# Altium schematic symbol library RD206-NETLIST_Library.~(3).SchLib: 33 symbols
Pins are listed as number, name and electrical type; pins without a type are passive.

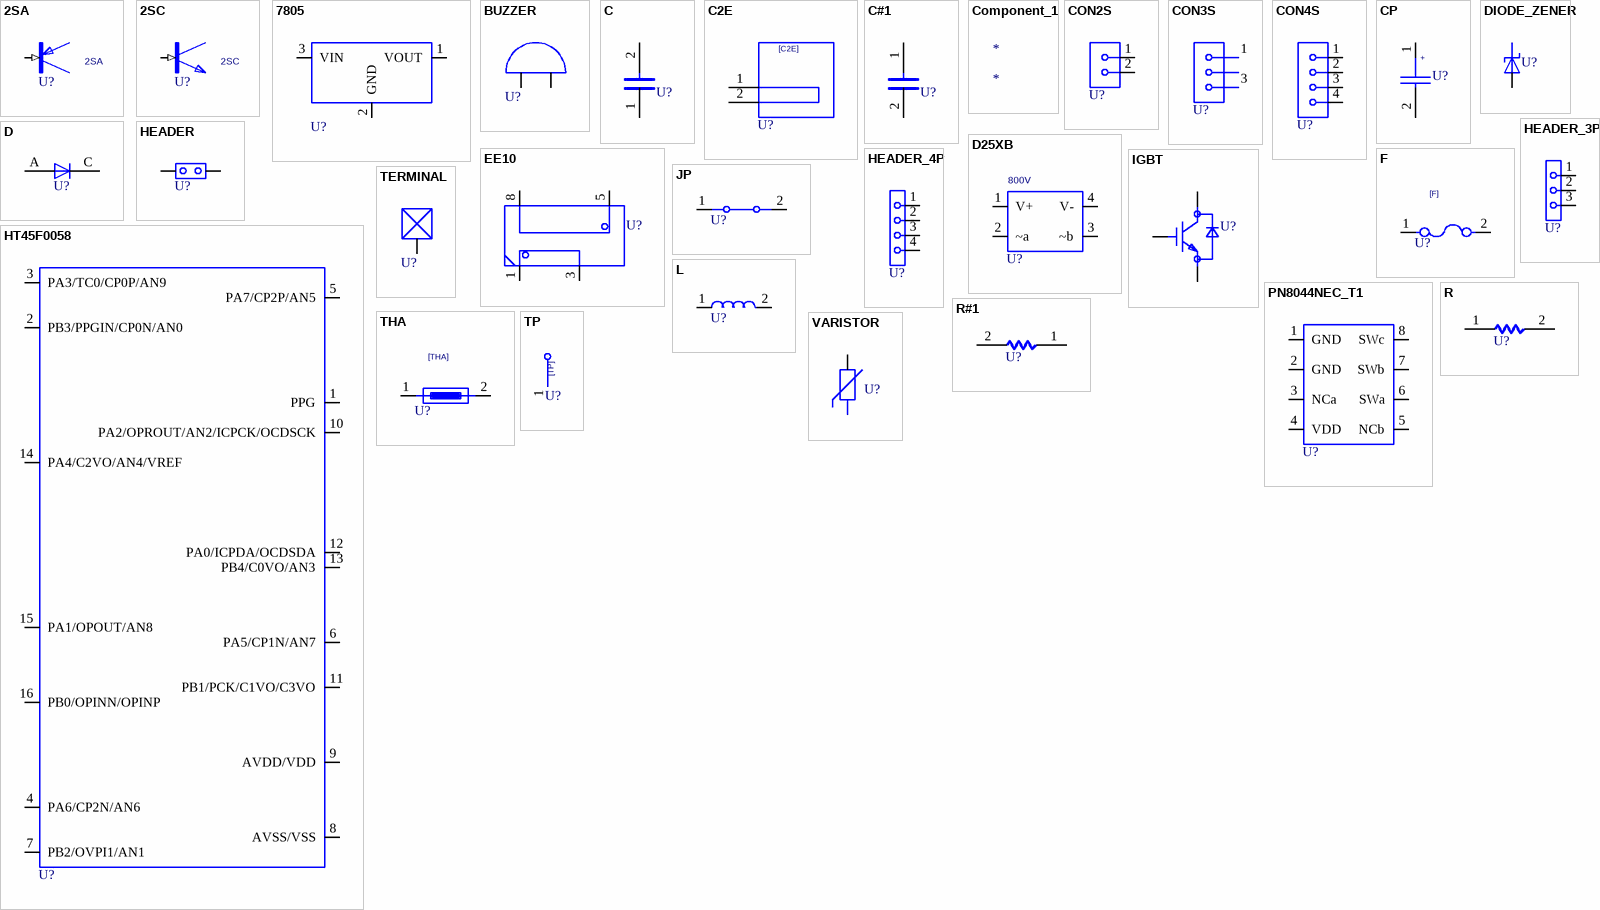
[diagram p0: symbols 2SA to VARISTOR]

## 2SA
designator U?
TIME: 16:07:41; UPDATEUSER: t5459927; SAVECOUNT: 1; OriginalSymbolOrigin: (0,2540); Altium-Right: 20; Altium-Bottom: 40
pins: 1 B (in), 2 E, 3 C

## 2SC
designator U?
TIME: 16:07:41; UPDATEUSER: t5459927; SAVECOUNT: 1; OriginalSymbolOrigin: (0,2540); Altium-Right: 20; Altium-Bottom: 40
pins: 1 B (in), 2 E, 3 C

## 7805
designator U?  (value not drawn)
TIME: 16:07:41; UPDATEUSER: t5459927; UPDATETIME: 09:17:01; SAVECOUNT: 2; SAVEAREA0: -5463,-13073,25154,1040; OriginalSymbolOrigin: (0,0); Altium-Right: 80; Altium-Bottom: 40
pins: 1 VOUT, 2 GND, 3 VIN

## BUZZER
designator U?  (value not drawn)
TIME: 16:07:41; UPDATEUSER: t5459927; SAVECOUNT: 1; OriginalSymbolOrigin: (0,0); Altium-Right: 40; Altium-Bottom: 20
pins: 1, 2

## C
designator U?  (value not drawn)
OriginalSymbolOrigin: (2540,7620); Altium-Right: 20; Altium-Bottom: 10
pins: 1, 2

## C2E
designator U?  (value not drawn)
SAVEAREA0: -4733,-209,25099,17942; TIME: 14:34:38; UPDATEUSER: fukuda-y; UPDATETIME: 16:35:06; SAVECOUNT: 10; OriginalSymbolOrigin: (5080,15240); Altium-Right: 50
pins: 1, 2

## C#1
designator U?, comment C  (value not drawn)
OriginalSymbolOrigin: (2540,7620); Altium-Right: 20; Altium-Bottom: 10
pins: 1 2, 2 1

## Component_1
designator *

## CON2S
designator U?  (value not drawn)
TIME: 16:07:41; UPDATEUSER: t5459927; UPDATETIME: 09:12:33; SAVECOUNT: 2; SAVEAREA0: -1901,-7788,9280,409; OriginalSymbolOrigin: (0,0); Altium-Right: 20; Altium-Bottom: 30
pins: 1, 2

## CON3S
designator U?  (value not drawn)
TIME: 16:07:41; UPDATEUSER: t5459927; UPDATETIME: 14:26:02; SAVECOUNT: 3; SAVEAREA0: -3803,-10405,11105,524; OriginalSymbolOrigin: (0,0); Altium-Right: 30; Altium-Bottom: 40
pins: 1, 3

## CON4S
designator U?  (value not drawn)
TIME: 16:07:41; UPDATEUSER: t5459927; UPDATETIME: 09:13:12; SAVECOUNT: 2; SAVEAREA0: -5711,-12954,12927,710; OriginalSymbolOrigin: (0,0); Altium-Right: 20; Altium-Bottom: 50
pins: 1, 2, 3, 4

## CP
designator U?  (value not drawn)
SAVEAREA0: -1450,-153,20294,13055; SAVECOUNT: 52; TIME: 15:02:55; UPDATEUSER: fukuda-y; UPDATETIME: 16:13:42; OriginalSymbolOrigin: (2540,10160); Altium-Right: 20
pins: 1 2, 2 1

## D
designator U?  (value not drawn)
SAVEAREA0: -225,-91,12804,7836; SAVECOUNT: 3; TIME: 14:49:55; UPDATEUSER: 19870035; UPDATETIME: 14:20:16; OriginalSymbolOrigin: (5080,5080); Altium-Right: 10; Altium-Bottom: 20
pins: A, C

## D25XB
designator U?  VALUE2: 800V  (hidden comment: D25XB)
TIME: 16:07:41; UPDATEUSER: t5459927; UPDATETIME: 09:10:23; SAVECOUNT: 2; SAVEAREA0: -3247,-11751,15521,2008; OriginalSymbolOrigin: (0,0); Altium-Right: 50; Altium-Bottom: 40
pins: 1 V+, 2 ~a, 3 ~b, 4 V-

## DIODE_ZENER
designator U?  (value not drawn)
PARTNAME: Diode-Zener; TIME: 16:07:41; UPDATEUSER: t5459927; SAVECOUNT: 1; OriginalSymbolOrigin: (0,0); Altium-Right: 20
pins: A Anode, C Cathode

## EE10
designator U?  (value not drawn)
TIME: 16:07:41; UPDATEUSER: t5459927; UPDATETIME: 09:16:10; SAVECOUNT: 2; SAVEAREA0: -29920,-23417,50107,13472; OriginalSymbolOrigin: (0,0); Altium-Right: 80; Altium-Bottom: 40
pins: 1, 3, 5, 8

## F
designator U?  (value not drawn)
OriginalSymbolOrigin: (2540,5080); Altium-Right: 40; Altium-Bottom: 20
pins: 1, 2

## HEADER
designator U?  (value not drawn)
TIME: 16:07:41; UPDATEUSER: t5459927; UPDATETIME: 09:13:58; SAVECOUNT: 2; SAVEAREA0: -2956,-6337,7768,1525; OriginalSymbolOrigin: (0,0); Altium-Right: 20
pins: 1, 2

## HEADER_3P
designator U?  (value not drawn)
TIME: 16:07:41; UPDATEUSER: t5459927; UPDATETIME: 09:13:29; SAVECOUNT: 2; SAVEAREA0: -5093,-10384,9816,546; OriginalSymbolOrigin: (0,0); Altium-Right: 10; Altium-Bottom: 40
pins: 1, 2, 3

## HEADER_4P
designator U?  (value not drawn)
TIME: 16:07:41; UPDATEUSER: t5459927; UPDATETIME: 09:13:44; SAVECOUNT: 2; SAVEAREA0: -6996,-12954,11642,710; OriginalSymbolOrigin: (0,0); Altium-Right: 10; Altium-Bottom: 50
pins: 1, 2, 3, 4

## HT45F0058
designator U?  (value not drawn)
MANUFACTURER: HOLTEK; TIME: 16:07:41; UPDATEUSER: t5459927; UPDATETIME: 09:12:11; SAVECOUNT: 2; SAVEAREA0: -96097,-76323,141060,32998; OriginalSymbolOrigin: (0,0); Altium-Right: 190; Altium-Bottom: 400
pins: 1 PPG, 2 PB3/PPGIN/CP0N/AN0, 3 PA3/TC0/CP0P/AN9, 4 PA6/CP2N/AN6, 5 PA7/CP2P/AN5, 6 PA5/CP1N/AN7, 7 PB2/OVPI1/AN1, 8 AVSS/VSS, 9 AVDD/VDD, 10 PA2/OPROUT/AN2/ICPCK/OCDSCK, 11 PB1/PCK/C1VO/C3VO, 12 PA0/ICPDA/OCDSDA, 13 PB4/C0VO/AN3, 14 PA4/C2VO/AN4/VREF, 15 PA1/OPOUT/AN8, 16 PB0/OPINN/OPINP

## IGBT
designator U?  (value not drawn)
TIME: 16:07:41; UPDATEUSER: t5459927; SAVECOUNT: 1; OriginalSymbolOrigin: (0,0); Altium-Right: 40
pins: 1 GATE, 2 COLLECTOR, 3 EMITTER

## JP
designator U?  (value not drawn)
OriginalSymbolOrigin: (2540,5080); Altium-Right: 40; Altium-Bottom: 20
pins: 1, 2

## L
designator U?  (value not drawn)
OriginalSymbolOrigin: (2540,5080); Altium-Right: 30; Altium-Bottom: 20
pins: 1, 2

## PN8044NEC_T1
designator U?  (value not drawn)
PARTNAME: PN8044NEC-T1; TIME: 16:07:41; UPDATEUSER: t5459927; UPDATETIME: 09:18:27; SAVECOUNT: 2; SAVEAREA0: -16422,-15263,31006,6599; OriginalSymbolOrigin: (0,0); Altium-Right: 60; Altium-Bottom: 80
pins: 1 GND, 2 GND, 3 NCa, 4 VDD, 5 NCb, 6 SWa, 7 SWb, 8 SWc

## R
designator U?  (value not drawn)
OriginalSymbolOrigin: (5080,5080); Altium-Right: 20
pins: 1, 2

## R#1
designator U?, comment R  (value not drawn)
OriginalSymbolOrigin: (5080,5080); Altium-Right: 20
pins: 1 2, 2 1

## TERMINAL
designator U?  (value not drawn)
TIME: 16:07:41; UPDATEUSER: t5459927; UPDATETIME: 09:10:57; SAVECOUNT: 2; SAVEAREA0: -3180,-7788,8001,409; OriginalSymbolOrigin: (0,0); Altium-Right: 20
pins: 1

## THA
designator U?  (value not drawn)
SAVECOUNT: 3; SAVEAREA0: -562,-143,15615,10489; TIME: 16:37:29; UPDATEUSER: sato-yr; OriginalSymbolOrigin: (2540,5080); Altium-Right: 40; Altium-Bottom: 20
pins: 1, 2

## TP
designator U?  (value not drawn)
TIME: 16:12:21; UPDATEUSER: fukuda-y; UPDATETIME: 16:18:11; SAVECOUNT: 2; SAVEAREA0: -242,-92,12810,7836; OriginalSymbolOrigin: (0,7620); Altium-Right: 20; Altium-Bottom: 30
pins: 1

## VARISTOR
designator U?  (value not drawn)
TIME: 16:07:41; UPDATEUSER: t5459927; UPDATETIME: 09:40:33; SAVECOUNT: 2; SAVEAREA0: -22723,-23461,27592,13427; OriginalSymbolOrigin: (0,-2540); Altium-Right: 20; Altium-Bottom: 30
pins: 1, 2

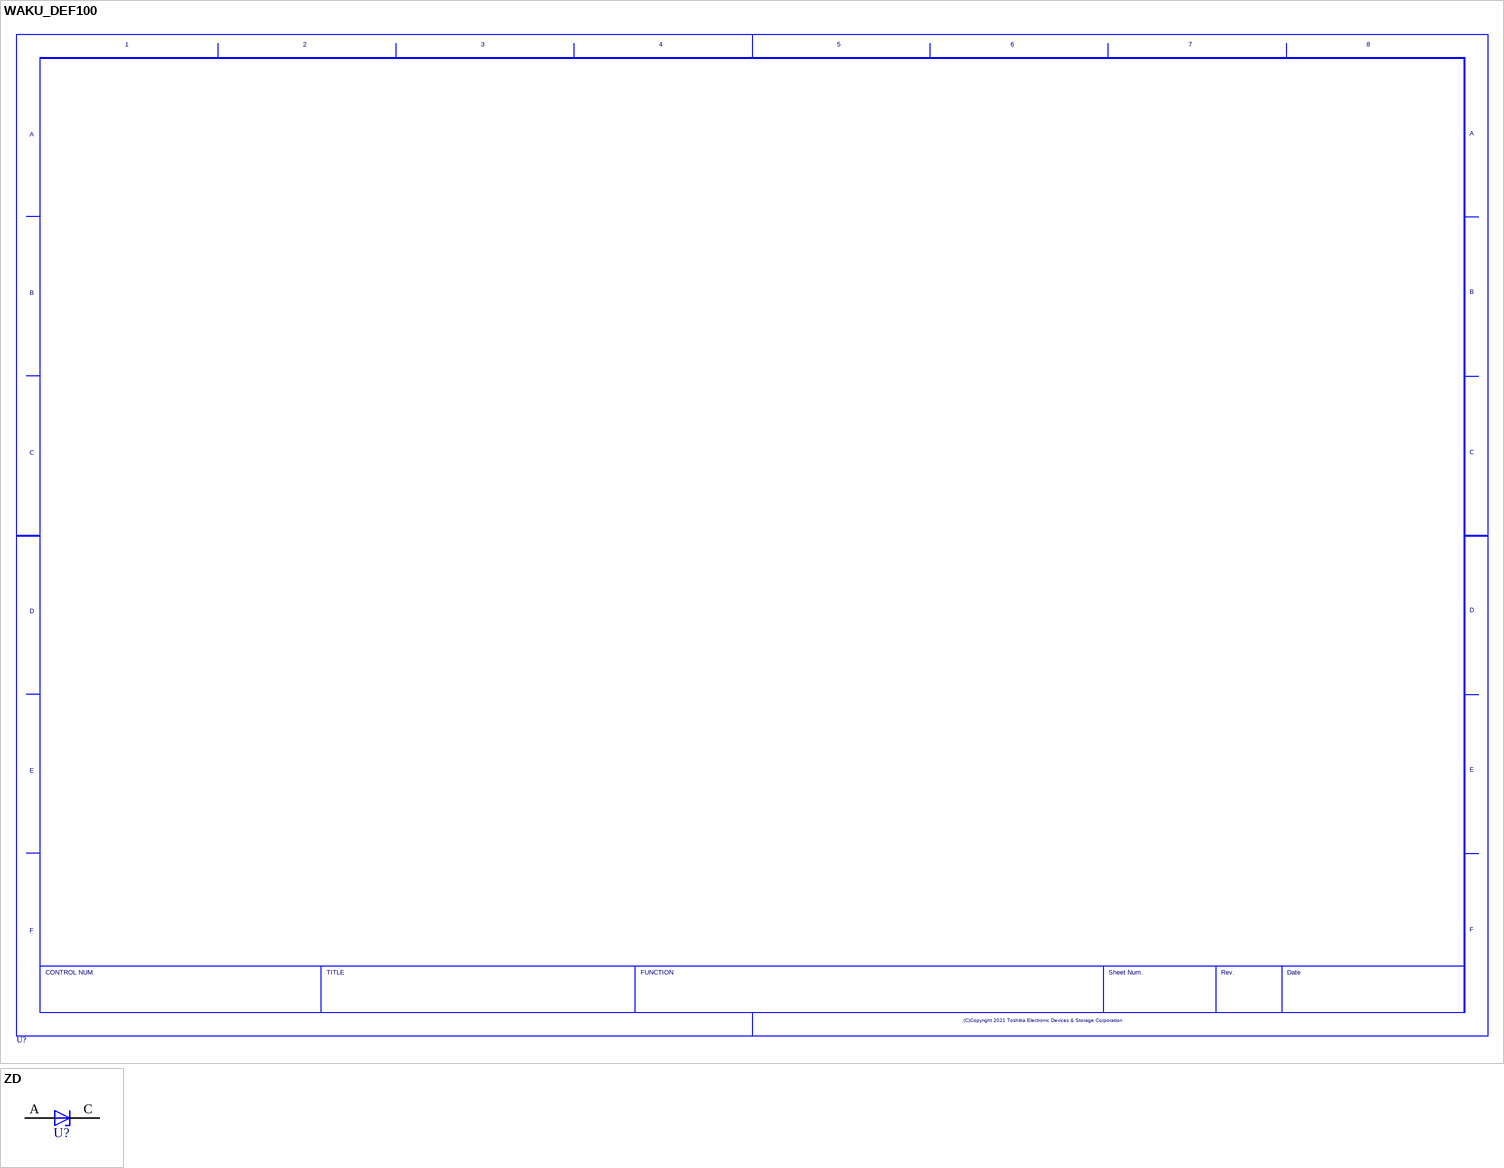
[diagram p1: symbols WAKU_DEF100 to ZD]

## WAKU_DEF100
designator U?  (value not drawn)
PLOTTIME: HH:MM; SAVEAREA0: 148187,-66180,486823,89919; TIME: 14:30:25; UPDATEUSER: t5459927; UPDATETIME: 11:46:11; SAVECOUNT: 6; OriginalSymbolOrigin: (10160,284480); Altium-Right: 1570; Altium-Bottom: 1070

## ZD
designator U?  (value not drawn)
SAVEAREA0: -4630,-153,17114,13055; TIME: 14:49:55; UPDATEUSER: fukuda-y; UPDATETIME: 08:18:42; SAVECOUNT: 6; OriginalSymbolOrigin: (5080,5080); Altium-Right: 10; Altium-Bottom: 20
pins: A, C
